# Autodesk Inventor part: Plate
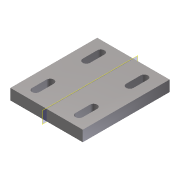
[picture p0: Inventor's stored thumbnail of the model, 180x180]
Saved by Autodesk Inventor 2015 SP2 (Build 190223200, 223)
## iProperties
Created: 2020-01
Part Number: Plate
Material: 一般
Document SubType Name: Modeling
Designer: Kuan_Lun Hsu
Density: 1 g/cm^3
Appearance: 預設
Author: Kuan_Lun Hsu
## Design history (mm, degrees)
node "Weld Bracket.sat1"
node "工作平面1"
node "實體1"
node "Base1"
